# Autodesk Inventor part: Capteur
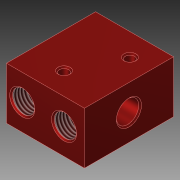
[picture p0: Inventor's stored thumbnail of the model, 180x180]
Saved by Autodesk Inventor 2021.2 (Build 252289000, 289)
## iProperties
Created: 2018-06
Part Number: Capteur
Material: Aluminium 6061
Document SubType Name: Modeling
Designer: Fabian Perrée
Density: 2.7 g/cm^3
Appearance: Anodisé - Rouge
Mass: 125.414 g
Surface Area: 130.388 cm^2
Volume: 46.4496 cm^3
Author: Fabian Perrée
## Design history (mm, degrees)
sketch "Esquisse1"
  geometry: L1 (-21, 24)-(21, 24); L2 (21, 24)-(21, -24); L3 (21, -24)-(-21, -24); L4 (-21, -24)-(-21, 24); L5 (-21, 24)-(21, -24); L6 (21, 24)-(-21, -24); 1 further point
  constraints: 12 end point, 2 midpoint, 2 parallel, 1 horizontal, 1 perpendicular
  dimensions: "d0" = 48 distance of L1.end L2.end; "d1" = 42 distance of L2.end L3.end
extrude "Extrusion1" new body sketch "Esquisse1" stored distance "d2" = 28; taper "d3" = 0 deg
sketch "Esquisse2"
  geometry: L1 (21, 24)-(21, -24) reference; L2 (21, 0)-(-21, 0); L3 (-21, 24)-(21, 24) reference; L4 (21, -24)-(-21, -24) reference; L5 (0, -24)-(0, 24); L6 (12.5, 24)-(12.5, 0); L7 (18.5, 24)-(18.5, 13); L8 (18.5, 13)-(17.75, 13); L9 (16.25, 11.5)-(16.25, 10); L10 (16.25, 10)-(14.5, 10); L11 (14.5, 10)-(14.5, 0); L12 (21, -6)-(8.5, -6); L13 (8.5, -6)-(8.5, -5.25); L14 (8.5, -5.25)-(5.5, -5.25); L15 (5.5, -5.25)-(5.5, -2.5); L16 (5.5, -2.5)-(0.5, -2.5); L17 (0.5, -2.5)-(0.5, -2); L18 (0.5, -2)-(-0.5, -2); L19 (-0.5, -2)-(-0.5, -6); L20 (-0.5, -6)-(-21, -6); L21 (-21, -24)-(-21, 24) reference; L22 (21, -6)-(21, 0); L23 (-21, -6)-(-21, 0); A1 r 1.5 centre (17.75, 11.5) between (17.75, 13) and (16.25, 11.5); 2 further points
  constraints: 38 end point, 12 perpendicular, 8 point on line, 3 horizontal, 3 midpoint, 2 point on circle, 2 tangent, 1 centre point, 1 collinear, 1 parallel, 1 vertical
  dimensions: "d6" = 12 diameter of L7 L6; "d7" = 8.5 distance between parallel lines of L1 L6; "d8" = 7.5 diameter of L9 L6; "d9" = 4 diameter of L11 L6; "d10" = 11 distance of L7.start L7.end; "d11" = 3 distance of point (16.25, 13) L9.end; "d12" = 1.5 radius of A1; "d19" = 12 diameter of L12 L2; "d20" = 10.5 diameter of L14 L2; "d21" = 5 diameter of L16 L2; "d22" = 4 diameter of L18 L2; "d23" = 1 distance of L17.end L18.end; "d24" = 12 diameter of L20 L2; "d25" = 12.5 distance of L12.start L12.end; "d26" = 15.5 distance between parallel lines of L15 L1; "d27" = 20.5 distance of L19.end L20.end
revolve "Révolution1" stored, may be unused: angle "d35" = 90 deg
sketch "Esquisse3"
  geometry: C1 r 6 at (8.5, -14) reference; 2 further points
  constraints: 1 horizontal alignment
  dimensions: "d36" = 22.5 distance of C1.centre point (31, -14)
sketch "Esquisse4"
  geometry: L1 (42, 0)-(42, -28) reference; 2 further points
  constraints: 1 horizontal alignment
  dimensions: "d37" = 18 distance from line of L1 point (24, -14)
feature "Filetage1" dims "d42" = 10, "d43" = 0
feature "Réseau basé sur une esquisse1"
feature "Réseau basé sur une esquisse2"
revolve "Révolution2" stored, may be unused: angle "d38" = 90 deg
feature "Filetage2" dims "d47" = 10, "d48" = 0
sketch "Esquisse5"
  geometry: C1 r 2.5 at (-24, 14) reference; C2 r 2 at (-24, 14) reference; 2 further points
  dimensions: "d49" = 19 horizontal distance of C1.centre point (-43, 5); "d50" = 9 vertical distance of C2.centre point (-43, 5); "d51" = 19 horizontal distance of point (-5, 23) C1.centre; "d52" = 9 vertical distance of point (-5, 23) C1.centre
hole "Perçage1" sketch "Esquisse5" at (-43, 5), (-5, 23) diameter "d53" = 4.134; stored, may be unused: countersink angle "d57" = 90 deg, drill point angle "d59" = 118 deg; dims "d54" = 10, "d55" = 4, "d56" = 2, "d58" = 12.5
sketch "Esquisse6"
  geometry: L1 (21, 24)-(-21, 24) reference; L2 (21, -24)-(21, 24) reference; L3 (-21, 24)-(-21, -24) reference; L4 (-21, -24)-(21, -24) reference; 3 further points
  dimensions: "d63" = 12 distance from line of L1 point (9.5, 12); "d65" = 19 distance from line of L3 point (-2, -12); "d66" = 12 distance from line of L4 point (-2, -12); "d74" = 30.5 distance from line of L3 point (9.5, 12)
hole "Perçage2" sketch "Esquisse6" at (9.5, 12), (-2, -12) diameter "d67" = 5; stored, may be unused: countersink angle "d71" = 90 deg, drill point angle "d73" = 118 deg; dims "d68" = 10, "d69" = 4, "d70" = 2, "d72" = 12.5
chamfer "Chanfrein4" distance "d75" = 0.75; stored, may be unused: second distance "d76" = 2, angle "d77" = 45 deg
feature "Scission1"
node "Solide1"
